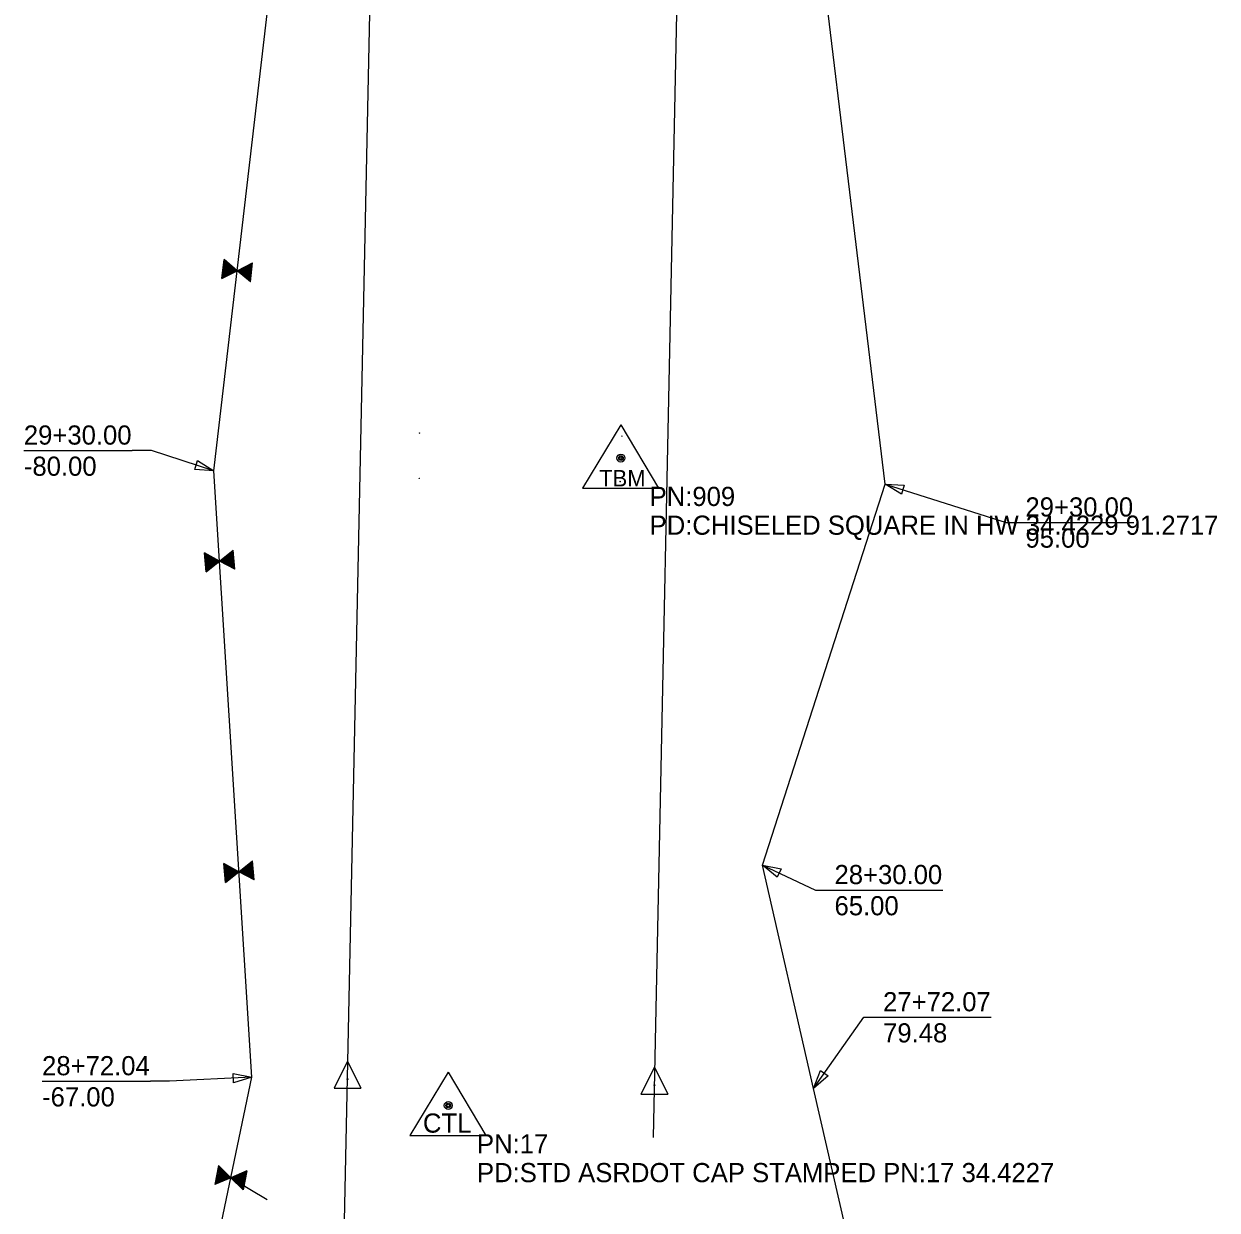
# Model space of a CAD drawing. Extents: x 1443798 to 1476449, y 2041559 to 2057889.
# Drawn here: x 1476114 to 1476425.1, y 2055477.1 to 2055786.4 of the extents above; entities that cross this region are included whole.
import ezdxf

# ---------------------------------------------------------------- set-up
doc = ezdxf.new("R2010")
doc.units = 0
for name, color, linetype in [('Plan Notes', 7, 'Continuous'), ('R_Proposed Fence', 7, 'Continuous'), ('R_ROW', 7, 'Continuous'), ('S_EXIST_ROW', 7, 'Continuous'), ('S_EXIST_ROW_ANNOT', 7, 'Continuous'), ('S_MSC_PT_SYM', 7, 'Continuous'), ('S_PRIMARY_CTL', 7, 'Continuous'), ('S_PRIMARY_CTL_ANNOT', 7, 'Continuous')]:
    doc.layers.add(name, color=color, linetype=linetype)

msp = doc.modelspace()

# ---------------------------------------------------------------- linework, layer by layer
at = {"layer": 'Plan Notes'}
for p, q in [((1476114.03, 2055675.16), (1476142.26, 2055675.16)), ((1476375.12, 2055656.4), (1476403.35, 2055656.4)), ((1476325.35, 2055560.54), (1476353.58, 2055560.54)), ((1476338.01, 2055527.37), (1476366.15, 2055527.37)), ((1476118.78, 2055510.69), (1476147.01, 2055510.69))]:
    msp.add_line(p, q, dxfattribs=at)
for points in [[(1476163.58, 2055669.9), (1476147.26, 2055675.16), (1476142.26, 2055675.16)], [(1476338.55, 2055666.44), (1476370.12, 2055656.4), (1476375.12, 2055656.4)], [(1476306.57, 2055567.05), (1476320.35, 2055560.54), (1476325.35, 2055560.54)], [(1476319.91, 2055508.84), (1476333.01, 2055527.37), (1476338.01, 2055527.37)], [(1476173.45, 2055511.72), (1476152.01, 2055510.69), (1476147.01, 2055510.69)]]:
    msp.add_lwpolyline(points, dxfattribs=at)
for points in [[(1476163.58, 2055669.9), (1476158.59, 2055670.23), (1476159.33, 2055672.54)], [(1476338.55, 2055666.44), (1476343.54, 2055666.13), (1476342.8, 2055663.81)], [(1476306.57, 2055567.05), (1476311.48, 2055566.08), (1476310.44, 2055563.88)], [(1476319.91, 2055508.84), (1476321.72, 2055513.51), (1476323.7, 2055512.1)], [(1476173.45, 2055511.72), (1476168.67, 2055510.27), (1476168.55, 2055512.7)]]:
    msp.add_lwpolyline(points, close=True, dxfattribs=at)
at = {"layer": 'R_Proposed Fence'}
for p, q in [((1476169.56, 2055722.05), (1476166.21, 2055724.89)), ((1476169.66, 2055722.07), (1476166.22, 2055724.99)), ((1476165.64, 2055720.02), (1476169.66, 2055722.07)), ((1476167.15, 2055720.81), (1476165.86, 2055721.91)), ((1476167.61, 2055721.08), (1476165.93, 2055722.5)), ((1476167.84, 2055721.22), (1476165.97, 2055722.8)), ((1476168.11, 2055721.31), (1476166, 2055723.1)), ((1476167.33, 2055720.99), (1476166.02, 2055722.1)), ((1476168.32, 2055721.46), (1476166.03, 2055723.4)), ((1476168.6, 2055721.55), (1476166.07, 2055723.7)), ((1476168.82, 2055721.69), (1476166.1, 2055724)), ((1476169.08, 2055721.8), (1476166.14, 2055724.29)), ((1476169.28, 2055721.95), (1476166.17, 2055724.59)), ((1476169.66, 2055722.07), (1476173.67, 2055724.12)), ((1476173.09, 2055719.16), (1476169.66, 2055722.07)), ((1476169.74, 2055722.02), (1476173.66, 2055724.02)), ((1476169.99, 2055721.87), (1476173.62, 2055723.73)), ((1476170.16, 2055721.67), (1476173.59, 2055723.43)), ((1476170.38, 2055721.51), (1476173.55, 2055723.13)), ((1476170.57, 2055721.32), (1476173.52, 2055722.83)), ((1476170.82, 2055721.17), (1476173.48, 2055722.53)), ((1476170.98, 2055720.97), (1476173.45, 2055722.23)), ((1476171.23, 2055720.82), (1476173.42, 2055721.94)), ((1476165.7, 2055720.07), (1476165.65, 2055720.12)), ((1476165.93, 2055720.21), (1476165.69, 2055720.42)), ((1476166.18, 2055720.32), (1476165.72, 2055720.71)), ((1476166.41, 2055720.46), (1476165.76, 2055721.01)), ((1476166.67, 2055720.57), (1476165.79, 2055721.31)), ((1476166.92, 2055720.68), (1476165.83, 2055721.61)), ((1476171.42, 2055720.63), (1476173.38, 2055721.64)), ((1476171.68, 2055720.49), (1476173.2, 2055721.26)), ((1476171.81, 2055720.27), (1476173.31, 2055721.04)), ((1476172, 2055720.09), (1476173.28, 2055720.74)), ((1476172.22, 2055719.92), (1476173.24, 2055720.44)), ((1476172.44, 2055719.76), (1476173.21, 2055720.14)), ((1476172.63, 2055719.57), (1476173.17, 2055719.85)), ((1476172.86, 2055719.4), (1476173.14, 2055719.55)), ((1476173.04, 2055719.22), (1476173.1, 2055719.25)), ((1476165.05, 2055646.35), (1476161.08, 2055648.48)), ((1476164.96, 2055646.3), (1476161.09, 2055648.38)), ((1476164.71, 2055646.15), (1476161.12, 2055648.08)), ((1476164.54, 2055645.96), (1476161.15, 2055647.78)), ((1476164.31, 2055645.8), (1476161.17, 2055647.48)), ((1476164.12, 2055645.62), (1476161.2, 2055647.18)), ((1476165.05, 2055646.35), (1476168.55, 2055649.19)), ((1476165.15, 2055646.32), (1476168.56, 2055649.09)), ((1476165.42, 2055646.22), (1476168.58, 2055648.79)), ((1476165.62, 2055646.06), (1476168.61, 2055648.49)), ((1476165.88, 2055645.94), (1476168.64, 2055648.19)), ((1476166.1, 2055645.8), (1476168.67, 2055647.9)), ((1476166.38, 2055645.71), (1476168.7, 2055647.6)), ((1476166.58, 2055645.55), (1476168.73, 2055647.3)), ((1476163.87, 2055645.47), (1476161.23, 2055646.88)), ((1476163.7, 2055645.27), (1476161.26, 2055646.59)), ((1476163.45, 2055645.13), (1476161.29, 2055646.29)), ((1476163.26, 2055644.94), (1476161.32, 2055645.99)), ((1476162.86, 2055644.59), (1476161.37, 2055645.39)), ((1476162.67, 2055644.41), (1476161.4, 2055645.09)), ((1476162.44, 2055644.25), (1476161.43, 2055644.79)), ((1476162.22, 2055644.09), (1476161.46, 2055644.49)), ((1476163, 2055644.8), (1476161.49, 2055645.61)), ((1476162.02, 2055643.9), (1476161.49, 2055644.19)), ((1476161.55, 2055643.5), (1476165.05, 2055646.35)), ((1476169.02, 2055644.21), (1476165.05, 2055646.35)), ((1476166.85, 2055645.45), (1476168.76, 2055647)), ((1476167.08, 2055645.31), (1476168.78, 2055646.7)), ((1476167.36, 2055645.22), (1476168.68, 2055646.29)), ((1476167.53, 2055645.03), (1476168.84, 2055646.1)), ((1476167.75, 2055644.89), (1476168.87, 2055645.8)), ((1476168.01, 2055644.78), (1476168.9, 2055645.5)), ((1476168.26, 2055644.66), (1476168.93, 2055645.2)), ((1476168.48, 2055644.52), (1476168.95, 2055644.9)), ((1476168.74, 2055644.41), (1476168.98, 2055644.61)), ((1476168.96, 2055644.26), (1476169.01, 2055644.31)), ((1476161.79, 2055643.74), (1476161.52, 2055643.89)), ((1476161.6, 2055643.56), (1476161.55, 2055643.59)), ((1476170.11, 2055565.34), (1476166.14, 2055567.47)), ((1476170.02, 2055565.29), (1476166.15, 2055567.37)), ((1476169.77, 2055565.14), (1476166.17, 2055567.07)), ((1476169.6, 2055564.95), (1476166.2, 2055566.77)), ((1476169.37, 2055564.79), (1476166.23, 2055566.48)), ((1476169.18, 2055564.61), (1476166.26, 2055566.18)), ((1476170.11, 2055565.34), (1476173.6, 2055568.18)), ((1476170.2, 2055565.31), (1476173.61, 2055568.08)), ((1476170.48, 2055565.21), (1476173.64, 2055567.79)), ((1476170.68, 2055565.05), (1476173.67, 2055567.49)), ((1476170.93, 2055564.94), (1476173.7, 2055567.19)), ((1476171.16, 2055564.8), (1476173.73, 2055566.89)), ((1476171.43, 2055564.7), (1476173.75, 2055566.59)), ((1476171.63, 2055564.54), (1476173.78, 2055566.29)), ((1476168.93, 2055564.46), (1476166.29, 2055565.88)), ((1476168.76, 2055564.27), (1476166.32, 2055565.58)), ((1476168.51, 2055564.12), (1476166.35, 2055565.28)), ((1476168.31, 2055563.94), (1476166.37, 2055564.98)), ((1476167.92, 2055563.58), (1476166.43, 2055564.38)), ((1476167.73, 2055563.4), (1476166.46, 2055564.08)), ((1476167.5, 2055563.24), (1476166.49, 2055563.78)), ((1476167.27, 2055563.08), (1476166.52, 2055563.49)), ((1476167.08, 2055562.9), (1476166.54, 2055563.19)), ((1476168.05, 2055563.79), (1476166.55, 2055564.6)), ((1476166.61, 2055562.49), (1476170.11, 2055565.34)), ((1476174.08, 2055563.21), (1476170.11, 2055565.34)), ((1476171.91, 2055564.44), (1476173.81, 2055565.99)), ((1476172.13, 2055564.3), (1476173.84, 2055565.69)), ((1476172.41, 2055564.21), (1476173.74, 2055565.29)), ((1476172.59, 2055564.03), (1476173.9, 2055565.09)), ((1476172.81, 2055563.89), (1476173.93, 2055564.8)), ((1476173.06, 2055563.77), (1476173.95, 2055564.5)), ((1476173.32, 2055563.66), (1476173.98, 2055564.2)), ((1476173.54, 2055563.51), (1476174.01, 2055563.9)), ((1476173.79, 2055563.4), (1476174.04, 2055563.6)), ((1476174.02, 2055563.26), (1476174.07, 2055563.3)), ((1476166.85, 2055562.74), (1476166.57, 2055562.89)), ((1476166.66, 2055562.56), (1476166.6, 2055562.59)), ((1476164.97, 2055488.42), (1476164.68, 2055488.3)), ((1476164.8, 2055488.62), (1476164.74, 2055488.59)), ((1476164.75, 2055488.68), (1476167.98, 2055485.54)), ((1476167.98, 2055485.54), (1476163.84, 2055483.77)), ((1476167.9, 2055485.59), (1476163.85, 2055483.87)), ((1476167.66, 2055485.76), (1476163.91, 2055484.16)), ((1476167.51, 2055485.97), (1476163.96, 2055484.46)), ((1476167.3, 2055486.15), (1476164.02, 2055484.75)), ((1476167.12, 2055486.35), (1476164.07, 2055485.05)), ((1476166.88, 2055486.52), (1476164.13, 2055485.34)), ((1476166.74, 2055486.72), (1476164.18, 2055485.64)), ((1476166.5, 2055486.89), (1476164.24, 2055485.93)), ((1476166.32, 2055487.09), (1476164.3, 2055486.23)), ((1476165.96, 2055487.48), (1476164.41, 2055486.82)), ((1476165.78, 2055487.68), (1476164.46, 2055487.11)), ((1476166.08, 2055487.26), (1476164.5, 2055486.59)), ((1476165.57, 2055487.86), (1476164.52, 2055487.41)), ((1476165.36, 2055488.04), (1476164.57, 2055487.7)), ((1476165.19, 2055488.24), (1476164.63, 2055488)), ((1476172.13, 2055487.3), (1476167.98, 2055485.54)), ((1476167.98, 2055485.54), (1476177.41, 2055479.84)), ((1476167.98, 2055485.54), (1476171.21, 2055482.39)), ((1476168.08, 2055485.56), (1476171.23, 2055482.49)), ((1476168.36, 2055485.63), (1476171.28, 2055482.78)), ((1476168.58, 2055485.77), (1476171.34, 2055483.08)), ((1476168.84, 2055485.86), (1476171.39, 2055483.37)), ((1476169.07, 2055485.98), (1476171.45, 2055483.67)), ((1476169.36, 2055486.05), (1476171.5, 2055483.96)), ((1476169.57, 2055486.19), (1476171.56, 2055484.26)), ((1476169.86, 2055486.27), (1476171.61, 2055484.55)), ((1476170.09, 2055486.39), (1476171.67, 2055484.85)), ((1476170.38, 2055486.45), (1476171.6, 2055485.26)), ((1476170.57, 2055486.62), (1476171.78, 2055485.44)), ((1476170.8, 2055486.74), (1476171.83, 2055485.73)), ((1476171.07, 2055486.83), (1476171.89, 2055486.03)), ((1476171.33, 2055486.92), (1476171.94, 2055486.33)), ((1476171.56, 2055487.05), (1476172, 2055486.62)), ((1476171.83, 2055487.14), (1476172.05, 2055486.92)), ((1476172.06, 2055487.26), (1476172.11, 2055487.21))]:
    msp.add_line(p, q, dxfattribs=at)
for points in [[(1476165.64, 2055720.02), (1476166.22, 2055724.99)], [(1476173.09, 2055719.16), (1476173.67, 2055724.12)], [(1476161.55, 2055643.5), (1476161.08, 2055648.48)], [(1476169.02, 2055644.21), (1476168.55, 2055649.19)], [(1476166.61, 2055562.49), (1476166.14, 2055567.47)], [(1476174.08, 2055563.21), (1476173.6, 2055568.18)], [(1476164.75, 2055488.68), (1476163.84, 2055483.77)], [(1476172.13, 2055487.3), (1476171.21, 2055482.39)]]:
    msp.add_lwpolyline(points, dxfattribs=at)
at = {"layer": 'R_ROW'}
for points in [[(1476186.62, 2054859.81), (1476148.84, 2054931.09), (1476150.62, 2055015.03), (1476181.31, 2055049.43), (1476148.04, 2055390.15), (1476173.45, 2055511.72), (1476163.58, 2055669.9), (1476210, 2056068.52)], [(1476266.59, 2054857.19), (1476319.08, 2054935.51), (1476286.09, 2055037.35), (1476312.02, 2055336.9), (1476343.4, 2055406.29), (1476319.91, 2055508.84), (1476306.57, 2055567.05), (1476338.55, 2055666.44), (1476290.01, 2056067.99)]]:
    msp.add_lwpolyline(points, dxfattribs=at)
at = {"layer": 'S_EXIST_ROW'}
for p, q in [((1476196.03, 2055396.48), (1476234.51, 2057247.25)), ((1476278.12, 2055496.04), (1476305.28, 2056802.66))]:
    msp.add_line(p, q, dxfattribs=at)
at = {"layer": 'S_EXIST_ROW_ANNOT'}
for p, q in [((1476198.43, 2055515.96), (1476194.9, 2055508.86)), ((1476198.43, 2055515.96), (1476201.91, 2055508.86)), ((1476278.41, 2055514.39), (1476274.89, 2055507.3)), ((1476278.41, 2055514.39), (1476281.9, 2055507.3)), ((1476198.41, 2055511.23), (1476198.41, 2055511.23)), ((1476194.9, 2055508.86), (1476201.91, 2055508.86)), ((1476274.89, 2055507.3), (1476281.9, 2055507.3)), ((1476278.4, 2055509.66), (1476278.4, 2055509.66))]:
    msp.add_line(p, q, dxfattribs=at)
for centre, radius in [((1476198.41, 2055511.23), 0.12), ((1476198.41, 2055511.23), 0.06), ((1476278.4, 2055509.66), 0.12), ((1476278.4, 2055509.66), 0.06)]:
    msp.add_circle(centre, radius, dxfattribs=at)
at = {"layer": 'S_MSC_PT_SYM'}
for points in [[(1476217.12, 2055679.74), (1476217.12, 2055679.79), (1476217.12, 2055679.74), (1476217.07, 2055679.74), (1476217.12, 2055679.74), (1476217.12, 2055679.69), (1476217.12, 2055679.74), (1476217.17, 2055679.74)], [(1476269.92, 2055678.93), (1476269.92, 2055678.98), (1476269.92, 2055678.93), (1476269.87, 2055678.93), (1476269.92, 2055678.93), (1476269.92, 2055678.88), (1476269.92, 2055678.93), (1476269.97, 2055678.93)], [(1476217.09, 2055667.96), (1476217.09, 2055668.01), (1476217.09, 2055667.96), (1476217.04, 2055667.96), (1476217.09, 2055667.96), (1476217.09, 2055667.91), (1476217.09, 2055667.96), (1476217.14, 2055667.96)], [(1476269.47, 2055667.1), (1476269.47, 2055667.15), (1476269.47, 2055667.1), (1476269.42, 2055667.1), (1476269.47, 2055667.1), (1476269.47, 2055667.05), (1476269.47, 2055667.1), (1476269.52, 2055667.1)]]:
    msp.add_lwpolyline(points, dxfattribs=at)
at = {"layer": 'S_PRIMARY_CTL'}
for p, q in [((1476269.65, 2055681.91), (1476259.62, 2055665.39)), ((1476269.65, 2055681.91), (1476279.48, 2055665.39)), ((1476259.62, 2055665.39), (1476279.48, 2055665.39)), ((1476224.65, 2055513.07), (1476214.62, 2055496.55)), ((1476224.65, 2055513.07), (1476234.48, 2055496.55)), ((1476214.62, 2055496.55), (1476234.48, 2055496.55))]:
    msp.add_line(p, q, dxfattribs=at)
for centre, radius in [((1476269.65, 2055673.21), 1.04), ((1476269.65, 2055673.21), 0.609), ((1476269.65, 2055673.21), 0.344), ((1476224.65, 2055504.37), 1.04), ((1476224.65, 2055504.37), 0.609), ((1476224.65, 2055504.37), 0.344)]:
    msp.add_circle(centre, radius, dxfattribs=at)

# ---------------------------------------------------------------- texts
at = {"layer": 'Plan Notes'}
for s, p in [('29+30.00', (1476114.03, 2055676.72)), ('-80.00', (1476114.03, 2055668.59)), ('29+30.00', (1476375.12, 2055657.96)), ('95.00', (1476375.12, 2055649.84)), ('28+30.00', (1476325.35, 2055562.1)), ('65.00', (1476325.35, 2055553.97)), ('27+72.07', (1476338.01, 2055528.93)), ('79.48', (1476338.01, 2055520.81)), ('28+72.04', (1476118.78, 2055512.25)), ('-67.00', (1476118.78, 2055504.12))]:
    msp.add_text(s, height=5, dxfattribs=at).set_placement(p)
at = {"layer": 'S_PRIMARY_CTL'}
msp.add_text('TBM', height=4.287, rotation=360, dxfattribs=at).set_placement((1476264, 2055665.82))
msp.add_text('CTL', height=5, dxfattribs=at).set_placement((1476218.06, 2055497.29))
at = {"layer": 'S_PRIMARY_CTL_ANNOT'}
for s, p in [('PN:909', (1476277.15, 2055660.71)), ('PD:CHISELED SQUARE IN HW 34.4229 91.2717', (1476277.15, 2055653.21)), ('PN:17', (1476232.15, 2055491.87)), ('PD:STD ASRDOT CAP STAMPED PN:17 34.4227', (1476232.15, 2055484.37))]:
    msp.add_text(s, height=5, dxfattribs=at).set_placement(p)

doc.saveas('drawing.dxf')
